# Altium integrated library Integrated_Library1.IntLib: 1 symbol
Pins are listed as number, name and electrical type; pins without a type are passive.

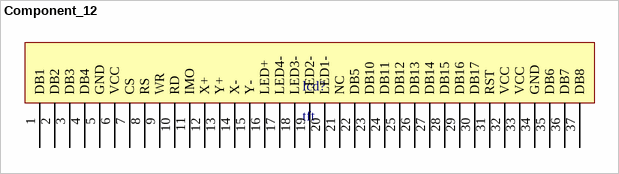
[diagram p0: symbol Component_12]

## Component_12
designator lcd?, comment tft
footprint PCBComponent_1
pins: 1 DB1, 2 DB2, 3 DB3, 4 DB4, 5 GND, 6 VCC, 7 CS, 8 RS, 9 WR, 10 RD, 11 IMO, 12 X+, 13 Y+, 14 X-, 15 Y-, 16 LED+, 17 LED4-, 18 LED3-, 19 LED2-, 20 LED1-, 21 NC, 22 DB5, 23 DB10, 24 DB11, 25 DB12, 26 DB13, 27 DB14, 28 DB15, 29 DB16, 30 DB17, 31 RST, 32 VCC, 33 VCC, 34 GND, 35 DB6, 36 DB7, 37 DB8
